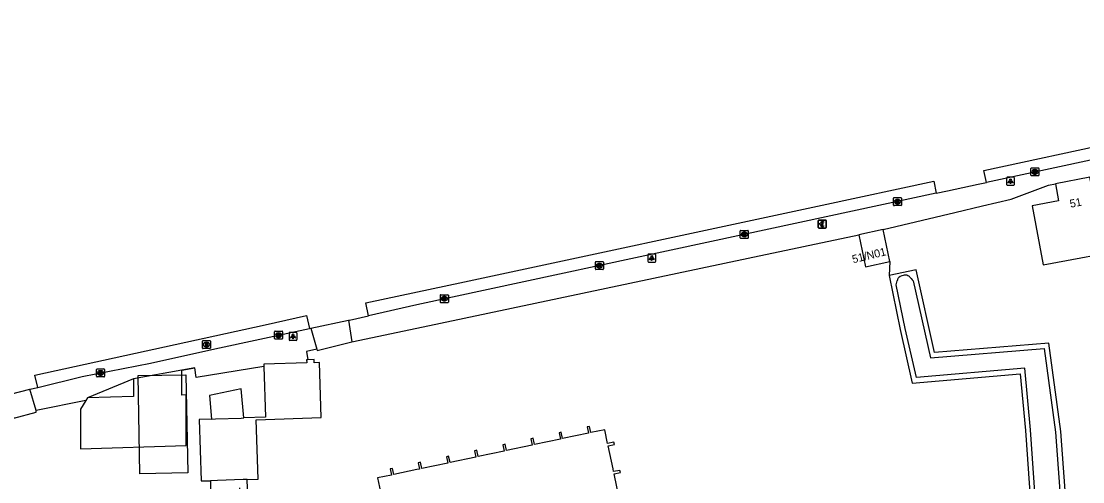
# Model space of a CAD drawing. Extents: x 161772 to 163123, y 383092 to 383917.
# Drawn here: x 161950.6 to 162083.2, y 383706.8 to 383764.3 of the extents above; entities that cross this region are included whole.
import ezdxf

# ---------------------------------------------------------------- set-up
doc = ezdxf.new("R2010")
doc.units = 0
for name, color, linetype in [('IMGEO_Betaalautomaat', 7, 'Continuous'), ('IMGEO_Erf', 7, 'Continuous'), ('IMGEO_Hek', 7, 'Continuous'), ('IMGEO_Kolk', 7, 'Continuous'), ('IMGEO_Lichtpunt', 7, 'Continuous'), ('IMGEO_Meer_plas_ven_vijver', 7, 'Continuous'), ('IMGEO_Muur', 7, 'Continuous'), ('IMGEO_Pand', 7, 'Continuous'), ('IMGEO_Pand_nummerreeks', 7, 'Continuous'), ('IMGEO_Pand_vergunning_verleend', 7, 'Continuous'), ('IMGEO_Rijbaan_lokaal_open', 7, 'Continuous'), ('IMGEO_Rioolput', 7, 'Continuous'), ('IMGEO_Voetpad_open', 7, 'Continuous'), ('IMGEO_Waterloop', 7, 'Continuous')]:
    doc.layers.add(name, color=color, linetype=linetype)

msp = doc.modelspace()

# ---------------------------------------------------------------- linework, layer by layer
at = {"layer": 'IMGEO_Betaalautomaat'}
for p, q in [((162050.16, 383738.51), (162050.16, 383739.36)), ((162050.16, 383739.36), (162050.16, 383738.51)), ((162050.23, 383739.44), (162051.07, 383739.44)), ((162051.07, 383739.44), (162050.23, 383739.44)), ((162051.08, 383738.44), (162050.24, 383738.44)), ((162050.24, 383738.44), (162051.08, 383738.44)), ((162050.44, 383738.9), (162050.44, 383738.97)), ((162050.56, 383738.97), (162050.56, 383738.9)), ((162050.82, 383739.24), (162050.8, 383739.14)), ((162050.81, 383738.74), (162050.83, 383738.65)), ((162051.16, 383739.37), (162051.16, 383738.52)), ((162051.16, 383738.52), (162051.16, 383739.37))]:
    msp.add_line(p, q, dxfattribs=at)
for points in [[(162050.44, 383738.97), (162050.37, 383738.97), (162050.37, 383739.04), (162050.45, 383739.04)], [(162050.45, 383738.83), (162050.37, 383738.83), (162050.37, 383738.9), (162050.44, 383738.9)], [(162050.57, 383739.04), (162050.72, 383739.04), (162050.72, 383738.97), (162050.56, 383738.97)], [(162050.56, 383738.9), (162050.72, 383738.9), (162050.72, 383738.83), (162050.57, 383738.83)]]:
    msp.add_lwpolyline(points, dxfattribs=at)
for centre, radius, start, end in [((162050.24, 383739.36), 0.0779, 92.4484, 184.2845), ((162050.24, 383739.36), 0.0779, 92.4484, 184.2845), ((162050.24, 383738.52), 0.0779, 182.4484, 274.2845), ((162050.24, 383738.52), 0.0779, 182.4484, 274.2845), ((162050.73, 383738.96), 0.293, 73.014, 165.0139), ((162050.71, 383738.89), 0.267, 191.8096, 297.0389), ((162050.74, 383738.98), 0.179, 69.3236, 159.5683), ((162050.74, 383738.9), 0.179, 202.7625, 291.8693), ((162051.08, 383739.36), 0.0779, 2.4484, 94.2845), ((162051.08, 383739.36), 0.0779, 2.4484, 94.2845), ((162051.08, 383738.52), 0.0779, 272.4484, 4.2845), ((162051.08, 383738.52), 0.0779, 272.4484, 4.2845)]:
    msp.add_arc(centre, radius, start, end, dxfattribs=at)
at = {"layer": 'IMGEO_Erf'}
for points in [[(162085.98, 383637.64), (162080.45, 383713.03), (162078.95, 383724.08), (162064.69, 383722.91), (162062.37, 383733.24), (162059, 383732.53), (162060.37, 383725.77), (162061.9, 383719.08), (162075.38, 383720.25), (162076.03, 383713.17), (162081.29, 383637.92)], [(161974.24, 383706.88), (161975.57, 383631.41)], [(161979.13, 383699.38), (161978.84, 383707.03)]]:
    msp.add_lwpolyline(points, dxfattribs=at)
at = {"layer": 'IMGEO_Hek'}
msp.add_lwpolyline([(162059.12, 383734.27), (162059, 383732.53)], dxfattribs=at)
at = {"layer": 'IMGEO_Kolk'}
for p, q in [((162076.73, 383745.03), (162076.73, 383745.89)), ((162076.8, 383745.96), (162077.65, 383745.96)), ((162077.21, 383745.74), (162077.24, 383745.74)), ((162077.24, 383745.18), (162077.21, 383745.18)), ((162077.73, 383745.89), (162077.73, 383745.03)), ((162077.65, 383744.96), (162076.8, 383744.96)), ((162059.56, 383741.31), (162059.56, 383742.16)), ((162059.63, 383742.24), (162060.48, 383742.24)), ((162060.48, 383741.24), (162059.63, 383741.24)), ((162060.04, 383742.02), (162060.07, 383742.02)), ((162060.07, 383741.46), (162060.04, 383741.46)), ((162060.56, 383742.16), (162060.56, 383741.31)), ((162040.42, 383737.22), (162040.42, 383738.08)), ((162040.49, 383738.15), (162041.35, 383738.15)), ((162041.35, 383737.15), (162040.49, 383737.15)), ((162040.91, 383737.93), (162040.93, 383737.93)), ((162040.93, 383737.37), (162040.91, 383737.37)), ((162041.42, 383738.08), (162041.42, 383737.22)), ((162022.32, 383733.33), (162022.32, 383734.18)), ((162022.39, 383734.26), (162023.25, 383734.26)), ((162023.25, 383733.25), (162022.39, 383733.25)), ((162022.83, 383733.48), (162022.8, 383733.48)), ((162022.81, 383734.03), (162022.83, 383734.03)), ((162023.32, 383734.18), (162023.32, 383733.33)), ((162002.95, 383729.19), (162002.95, 383730.04)), ((162003.02, 383730.12), (162003.88, 383730.12)), ((162003.88, 383729.12), (162003.02, 383729.12)), ((162003.46, 383729.34), (162003.43, 383729.34)), ((162003.44, 383729.9), (162003.46, 383729.9)), ((162003.95, 383730.04), (162003.95, 383729.19)), ((161982.24, 383724.64), (161982.24, 383725.49)), ((161982.32, 383725.56), (161983.17, 383725.56)), ((161982.73, 383725.34), (161982.75, 383725.34)), ((161983.24, 383725.49), (161983.24, 383724.64)), ((161983.17, 383724.56), (161982.32, 383724.56)), ((161982.75, 383724.78), (161982.73, 383724.78)), ((161960, 383719.93), (161960, 383720.78)), ((161960.08, 383720.85), (161960.93, 383720.85)), ((161960.93, 383719.85), (161960.08, 383719.85)), ((161960.49, 383720.63), (161960.52, 383720.63)), ((161960.51, 383720.07), (161960.49, 383720.07)), ((161961, 383720.78), (161961, 383719.93))]:
    msp.add_line(p, q, dxfattribs=at)
for points in [[(162076.73, 383745.03), (162076.73, 383745.89)], [(162076.8, 383745.96), (162077.65, 383745.96)], [(162077.05, 383745.66), (162077.17, 383745.66), (162077.17, 383745.51), (162077.3, 383745.66), (162077.46, 383745.66), (162077.32, 383745.51), (162077.47, 383745.26), (162077.32, 383745.26), (162077.23, 383745.42), (162077.17, 383745.36), (162077.17, 383745.26), (162077.05, 383745.26), (162077.05, 383745.66)], [(162077.73, 383745.89), (162077.73, 383745.03)], [(162077.65, 383744.96), (162076.8, 383744.96)], [(162059.56, 383741.31), (162059.56, 383742.16)], [(162059.63, 383742.24), (162060.48, 383742.24)], [(162060.48, 383741.24), (162059.63, 383741.24)], [(162059.88, 383741.94), (162060, 383741.94), (162060, 383741.79), (162060.13, 383741.94), (162060.29, 383741.94), (162060.15, 383741.79), (162060.3, 383741.54), (162060.15, 383741.54), (162060.06, 383741.7), (162060, 383741.63), (162060, 383741.54), (162059.88, 383741.54), (162059.88, 383741.94)], [(162060.56, 383742.16), (162060.56, 383741.31)], [(162040.42, 383737.22), (162040.42, 383738.08)], [(162040.49, 383738.15), (162041.35, 383738.15)], [(162041.35, 383737.15), (162040.49, 383737.15)], [(162040.74, 383737.85), (162040.86, 383737.85), (162040.86, 383737.7), (162040.99, 383737.85), (162041.16, 383737.85), (162041.01, 383737.7), (162041.16, 383737.45), (162041.01, 383737.45), (162040.93, 383737.61), (162040.86, 383737.55), (162040.86, 383737.45), (162040.74, 383737.45), (162040.74, 383737.85)], [(162041.42, 383738.08), (162041.42, 383737.22)], [(162022.32, 383733.33), (162022.32, 383734.18)], [(162022.39, 383734.26), (162023.25, 383734.26)], [(162023.25, 383733.25), (162022.39, 383733.25)], [(162022.64, 383733.95), (162022.76, 383733.95), (162022.76, 383733.8), (162022.89, 383733.95), (162023.06, 383733.95), (162022.91, 383733.8), (162023.06, 383733.55), (162022.91, 383733.55), (162022.83, 383733.72), (162022.76, 383733.65), (162022.76, 383733.55), (162022.64, 383733.55), (162022.64, 383733.95)], [(162023.32, 383734.18), (162023.32, 383733.33)], [(162002.95, 383729.19), (162002.95, 383730.04)], [(162003.02, 383730.12), (162003.88, 383730.12)], [(162003.88, 383729.12), (162003.02, 383729.12)], [(162003.27, 383729.82), (162003.39, 383729.82), (162003.39, 383729.66), (162003.52, 383729.82), (162003.69, 383729.82), (162003.54, 383729.67), (162003.69, 383729.42), (162003.54, 383729.42), (162003.46, 383729.58), (162003.39, 383729.51), (162003.39, 383729.42), (162003.27, 383729.42), (162003.27, 383729.82)], [(162003.95, 383730.04), (162003.95, 383729.19)], [(161982.24, 383724.64), (161982.24, 383725.49)], [(161982.32, 383725.56), (161983.17, 383725.56)], [(161982.56, 383725.26), (161982.69, 383725.26), (161982.69, 383725.11), (161982.81, 383725.26), (161982.98, 383725.26), (161982.83, 383725.11), (161982.99, 383724.86), (161982.83, 383724.86), (161982.75, 383725.03), (161982.69, 383724.96), (161982.69, 383724.86), (161982.56, 383724.86), (161982.56, 383725.26)], [(161983.24, 383725.49), (161983.24, 383724.64)], [(161983.17, 383724.56), (161982.32, 383724.56)], [(161960, 383719.93), (161960, 383720.78)], [(161960.08, 383720.85), (161960.93, 383720.85)], [(161960.93, 383719.85), (161960.08, 383719.85)], [(161960.32, 383720.55), (161960.45, 383720.55), (161960.45, 383720.4), (161960.58, 383720.55), (161960.74, 383720.55), (161960.6, 383720.4), (161960.75, 383720.15), (161960.6, 383720.15), (161960.51, 383720.32), (161960.45, 383720.25), (161960.45, 383720.15), (161960.32, 383720.15), (161960.32, 383720.55)], [(161961, 383720.78), (161961, 383719.93)]]:
    msp.add_lwpolyline(points, dxfattribs=at)
for centre, start, end in [((162076.8, 383745.88), 91.552, 178.448), ((162076.8, 383745.88), 91.552, 178.448), ((162076.8, 383745.04), 181.552, 268.448), ((162076.8, 383745.04), 181.552, 268.448), ((162077.65, 383745.88), 1.552, 88.448), ((162077.65, 383745.88), 1.552, 88.448), ((162077.65, 383745.04), 271.552, 358.448), ((162077.65, 383745.04), 271.552, 358.448), ((162059.63, 383742.16), 91.552, 178.448), ((162059.63, 383742.16), 91.552, 178.448), ((162059.63, 383741.31), 181.552, 268.448), ((162059.63, 383741.31), 181.552, 268.448), ((162060.48, 383742.16), 1.552, 88.448), ((162060.48, 383742.16), 1.552, 88.448), ((162060.48, 383741.31), 271.552, 358.448), ((162060.48, 383741.31), 271.552, 358.448), ((162040.5, 383738.07), 91.552, 178.448), ((162040.5, 383738.07), 91.552, 178.448), ((162040.5, 383737.22), 181.552, 268.448), ((162040.5, 383737.22), 181.552, 268.448), ((162041.34, 383738.07), 1.552, 88.448), ((162041.34, 383738.07), 1.552, 88.448), ((162041.34, 383737.22), 271.552, 358.448), ((162041.34, 383737.22), 271.552, 358.448), ((162022.39, 383734.18), 91.552, 178.448), ((162022.39, 383734.18), 91.552, 178.448), ((162022.39, 383733.33), 181.552, 268.448), ((162022.39, 383733.33), 181.552, 268.448), ((162023.24, 383734.18), 1.552, 88.448), ((162023.24, 383734.18), 1.552, 88.448), ((162023.24, 383733.33), 271.552, 358.448), ((162023.24, 383733.33), 271.552, 358.448), ((162003.02, 383730.04), 91.552, 178.448), ((162003.02, 383730.04), 91.552, 178.448), ((162003.02, 383729.19), 181.552, 268.448), ((162003.02, 383729.19), 181.552, 268.448), ((162003.87, 383730.04), 1.552, 88.448), ((162003.87, 383730.04), 1.552, 88.448), ((162003.87, 383729.19), 271.552, 358.448), ((162003.87, 383729.19), 271.552, 358.448), ((161982.32, 383725.49), 91.552, 178.448), ((161982.32, 383725.49), 91.552, 178.448), ((161983.17, 383725.49), 1.552, 88.448), ((161983.17, 383725.49), 1.552, 88.448), ((161982.32, 383724.64), 181.552, 268.448), ((161982.32, 383724.64), 181.552, 268.448), ((161983.17, 383724.64), 271.552, 358.448), ((161983.17, 383724.64), 271.552, 358.448), ((161960.08, 383720.78), 91.552, 178.448), ((161960.08, 383720.78), 91.552, 178.448), ((161960.08, 383719.93), 181.552, 268.448), ((161960.08, 383719.93), 181.552, 268.448), ((161960.93, 383720.78), 1.552, 88.448), ((161960.93, 383720.78), 1.552, 88.448), ((161960.93, 383719.93), 271.552, 358.448), ((161960.93, 383719.93), 271.552, 358.448)]:
    msp.add_arc(centre, 0.0765, start, end, dxfattribs=at)
for centre, major_axis, ratio, start_param, end_param in [((162077.21, 383745.46), (-0.387, 0.002), 0.722429, 4.712389, 7.853982), ((162077.24, 383745.46), (-0.39, 0.002), 0.717154, 1.570796, 4.712389), ((162060.04, 383741.74), (-0.387, 0.002), 0.722429, 4.712389, 7.853982), ((162060.07, 383741.74), (-0.39, 0.002), 0.717154, 1.570796, 4.712389), ((162040.91, 383737.65), (-0.387, 0.002), 0.722429, 4.712389, 7.853982), ((162040.93, 383737.65), (-0.39, 0.002), 0.717154, 1.570796, 4.712389), ((162022.81, 383733.75), (-0.387, 0.002), 0.722429, 4.712389, 7.853982), ((162022.83, 383733.75), (-0.39, 0.002), 0.717154, 1.570796, 4.712389), ((162003.44, 383729.62), (-0.387, 0.002), 0.722429, 4.712389, 7.853982), ((162003.46, 383729.62), (-0.39, 0.002), 0.717154, 1.570796, 4.712389), ((161982.73, 383725.06), (-0.387, 0.002), 0.722429, 4.712389, 7.853982), ((161982.75, 383725.06), (-0.39, 0.002), 0.717154, 1.570796, 4.712389), ((161960.49, 383720.35), (-0.387, 0.002), 0.722429, 4.712389, 7.853982), ((161960.51, 383720.35), (-0.39, 0.002), 0.717154, 1.570796, 4.712389)]:
    msp.add_ellipse(centre, major_axis=major_axis, ratio=ratio, start_param=start_param, end_param=end_param, dxfattribs=at)
at = {"layer": 'IMGEO_Lichtpunt'}
for p, q in [((162073.67, 383744.69), (162073.67, 383743.89)), ((162073.67, 383744.69), (162073.67, 383743.89)), ((162074.58, 383744.79), (162073.77, 383744.79)), ((162074.58, 383744.79), (162073.77, 383744.79)), ((162073.77, 383743.79), (162074.58, 383743.79)), ((162073.77, 383743.79), (162074.58, 383743.79)), ((162074.67, 383743.89), (162074.67, 383744.69)), ((162074.67, 383743.89), (162074.67, 383744.69)), ((162028.87, 383735.1), (162028.87, 383734.29)), ((162028.87, 383735.1), (162028.87, 383734.29)), ((162029.77, 383735.19), (162028.96, 383735.19)), ((162029.77, 383735.19), (162028.96, 383735.19)), ((162029.86, 383734.29), (162029.86, 383735.1)), ((162029.86, 383734.29), (162029.86, 383735.1)), ((162028.96, 383734.2), (162029.77, 383734.2)), ((162028.96, 383734.2), (162029.77, 383734.2)), ((161984.05, 383725.32), (161984.05, 383724.51)), ((161984.05, 383725.32), (161984.05, 383724.51)), ((161984.95, 383725.41), (161984.15, 383725.41)), ((161984.95, 383725.41), (161984.15, 383725.41)), ((161985.05, 383724.51), (161985.05, 383725.32)), ((161985.05, 383724.51), (161985.05, 383725.32)), ((161984.15, 383724.42), (161984.95, 383724.42)), ((161984.15, 383724.42), (161984.95, 383724.42))]:
    msp.add_line(p, q, dxfattribs=at)
for points in [[(162074.05, 383744.36), (162074.09, 383744.33), (162073.9, 383744.07), (162073.86, 383744.1), (162074.05, 383744.36)], [(162074.15, 383744.31), (162074.2, 383744.31), (162074.2, 383743.99), (162074.15, 383743.99), (162074.15, 383744.31)], [(162074.26, 383744.33), (162074.3, 383744.36), (162074.49, 383744.09), (162074.45, 383744.07), (162074.26, 383744.33)], [(162029.24, 383734.76), (162029.28, 383734.74), (162029.09, 383734.47), (162029.05, 383734.5), (162029.24, 383734.76)], [(162029.34, 383734.72), (162029.39, 383734.72), (162029.39, 383734.39), (162029.34, 383734.39), (162029.34, 383734.72)], [(162029.45, 383734.74), (162029.49, 383734.76), (162029.68, 383734.5), (162029.64, 383734.47), (162029.45, 383734.74)], [(161984.43, 383724.98), (161984.46, 383724.96), (161984.28, 383724.69), (161984.24, 383724.72), (161984.43, 383724.98)], [(161984.53, 383724.94), (161984.58, 383724.94), (161984.58, 383724.61), (161984.53, 383724.61), (161984.53, 383724.94)], [(161984.64, 383724.96), (161984.68, 383724.98), (161984.86, 383724.72), (161984.82, 383724.69), (161984.64, 383724.96)]]:
    msp.add_lwpolyline(points, dxfattribs=at)
for centre in [(162074.17, 383744.49), (162029.37, 383734.9), (161984.55, 383725.12)]:
    msp.add_circle(centre, 0.0994, dxfattribs=at)
for centre, start, end in [((162073.77, 383744.69), 90, 180), ((162073.77, 383744.69), 90, 180), ((162073.77, 383743.89), 180, 270), ((162073.77, 383743.89), 180, 270), ((162074.58, 383744.69), 0, 90), ((162074.58, 383744.69), 0, 90), ((162074.58, 383743.89), 270, 0), ((162074.58, 383743.89), 270, 360), ((162028.96, 383735.1), 90, 180), ((162028.96, 383735.1), 90, 180), ((162029.77, 383735.1), 0, 90), ((162029.77, 383735.1), 0, 90), ((162028.96, 383734.29), 180, 270), ((162028.96, 383734.29), 180, 270), ((162029.77, 383734.29), 270, 0), ((162029.77, 383734.29), 270, 360), ((161984.15, 383725.32), 90, 180), ((161984.15, 383725.32), 90, 180), ((161984.95, 383725.32), 0, 90), ((161984.95, 383725.32), 0, 90), ((161984.15, 383724.51), 180, 270), ((161984.15, 383724.51), 180, 270), ((161984.95, 383724.51), 270, 0), ((161984.95, 383724.51), 270, 360)]:
    msp.add_arc(centre, 0.0946, start, end, dxfattribs=at)
at = {"layer": 'IMGEO_Meer_plas_ven_vijver'}
msp.add_lwpolyline([(161978.4, 383714.72), (161978.07, 383718.37), (161974.11, 383717.54), (161974.35, 383714.59)], dxfattribs=at)
at = {"layer": 'IMGEO_Muur'}
for points in [[(161970.65, 383720.71), (161972.28, 383721)], [(161958.68, 383716.9), (161952.45, 383715.66)]]:
    msp.add_lwpolyline(points, dxfattribs=at)
at = {"layer": 'IMGEO_Pand'}
for points in [[(162079.78, 383743.97), (162080.18, 383741.83), (162076.86, 383741.21), (162078.24, 383733.84), (162089.44, 383735.94), (162088.06, 383743.31), (162084.49, 383742.64), (162084.08, 383744.78)], [(162084.08, 383744.78), (162079.78, 383743.97)], [(162058.26, 383738.28), (162055.21, 383737.6)], [(162055.21, 383737.6), (162056.08, 383733.59), (162059.12, 383734.27), (162058.26, 383738.28)], [(161980.92, 383721.17), (161981.13, 383714.81), (161978.4, 383714.72)], [(161978.84, 383707.03), (161980.18, 383707.08), (161979.94, 383714.49), (161988.08, 383714.76), (161987.86, 383721.65), (161987.2, 383721.62), (161987.19, 383722.03), (161986.38, 383722)], [(161986.38, 383722), (161986.25, 383721.99), (161986.27, 383721.61), (161980.91, 383721.44), (161980.92, 383721.17)], [(161958.68, 383716.9), (161958.02, 383715.83), (161958.02, 383710.88), (161971.22, 383711.27), (161971.22, 383717.6), (161970.64, 383717.58), (161970.65, 383720.71)], [(161970.65, 383720.71), (161964.64, 383719.62)], [(161964.64, 383719.62), (161964.64, 383717.4), (161958.89, 383717.23)], [(161958.89, 383717.23), (161958.68, 383716.9)], [(161974.35, 383714.59), (161972.84, 383714.54), (161973.09, 383706.85), (161974.24, 383706.88)], [(161974.35, 383714.59), (161974.85, 383714.6), (161978.09, 383714.71), (161978.4, 383714.72)], [(162025.35, 383704.49), (162024.66, 383707.74), (162025.45, 383707.91), (162025.39, 383708.18), (162024.6, 383708.02), (162024.52, 383708.37), (162023.91, 383711.25), (162024.69, 383711.42), (162024.63, 383711.7), (162023.85, 383711.53), (162023.48, 383713.26), (162021.74, 383712.89), (162021.58, 383713.67), (162021.3, 383713.61), (162021.47, 383712.83), (162018.23, 383712.14), (162018.06, 383712.93), (162017.78, 383712.87), (162017.95, 383712.08), (162014.72, 383711.4), (162014.55, 383712.19), (162014.26, 383712.12), (162014.43, 383711.33), (162011.21, 383710.65), (162011.04, 383711.44), (162010.75, 383711.38), (162010.92, 383710.59), (162007.69, 383709.9), (162007.52, 383710.68), (162007.23, 383710.62), (162007.4, 383709.84), (162004.16, 383709.15), (162003.99, 383709.94), (162003.72, 383709.88), (162003.88, 383709.09), (162000.64, 383708.4), (162000.48, 383709.19), (162000.19, 383709.13), (162000.36, 383708.34), (162000, 383708.27), (161997.14, 383707.66), (161996.97, 383708.43), (161996.68, 383708.38), (161996.84, 383707.59), (161995.12, 383707.23), (161995.48, 383705.51)], [(161978.84, 383707.03), (161978.32, 383707.02), (161975.12, 383706.91), (161974.24, 383706.88)]]:
    msp.add_lwpolyline(points, dxfattribs=at)
at = {"layer": 'IMGEO_Pand_vergunning_verleend'}
msp.add_lwpolyline([(161965.2, 383720.02), (161971.16, 383720.13), (161971.39, 383707.87), (161965.43, 383707.75), (161965.2, 383720.02)], dxfattribs=at)
at = {"layer": 'IMGEO_Rijbaan_lokaal_open'}
for points in [[(162071.16, 383744.13), (162070.83, 383745.65), (162087.46, 383749.22), (162116.59, 383755.47), (162143.1, 383761.16), (162157.04, 383764.27), (162157.36, 383762.66)], [(161993.98, 383727.48), (161993.66, 383729.1), (162005.96, 383731.73), (162050.66, 383741.32), (162064.6, 383744.31), (162064.89, 383742.78)], [(162064.89, 383742.78), (162066.3, 383743.09), (162070.13, 383743.91), (162071.16, 383744.13)], [(161952.65, 383718.54), (161952.31, 383720.05), (161981.08, 383726.37), (161986.25, 383727.5), (161986.59, 383725.88)], [(161986.77, 383725.92), (161991.47, 383726.92)], [(161991.47, 383726.92), (161991.61, 383726.95), (161993.98, 383727.48)], [(161986.59, 383725.88), (161986.77, 383725.92)], [(161951.69, 383718.3), (161952.65, 383718.54)], [(161947.93, 383717.38), (161951.69, 383718.3)]]:
    msp.add_lwpolyline(points, dxfattribs=at)
at = {"layer": 'IMGEO_Rioolput'}
for p, q in [((161973.24, 383723.46), (161973.24, 383724.32)), ((161973.31, 383724.39), (161974.16, 383724.39)), ((161973.72, 383724.17), (161973.75, 383724.17)), ((161974.24, 383724.32), (161974.24, 383723.46)), ((161974.16, 383723.39), (161973.31, 383723.39)), ((161973.75, 383723.61), (161973.72, 383723.61))]:
    msp.add_line(p, q, dxfattribs=at)
for points in [[(161973.24, 383723.46), (161973.24, 383724.32)], [(161973.31, 383724.39), (161974.16, 383724.39)], [(161973.82, 383724.09), (161973.57, 383724.09), (161973.57, 383723.69)], [(161973.57, 383723.69), (161973.7, 383723.69), (161973.7, 383723.85), (161973.71, 383723.85)], [(161973.75, 383724.01), (161973.7, 383724.01), (161973.7, 383723.93)], [(161973.7, 383723.93), (161973.75, 383723.93)], [(161973.75, 383723.82), (161973.83, 383723.69), (161973.96, 383723.69), (161973.9, 383723.82)], [(161974.24, 383724.32), (161974.24, 383723.46)], [(161974.16, 383723.39), (161973.31, 383723.39)]]:
    msp.add_lwpolyline(points, dxfattribs=at)
for centre, radius, start, end in [((161973.31, 383724.32), 0.0765, 91.552, 178.448), ((161973.31, 383724.32), 0.0765, 91.552, 178.448), ((161973.71, 383723.8), 0.0533, 26.0293, 88.6989), ((161973.76, 383723.91), 0.0964, 77.0061, 93.1865), ((161973.73, 383724.12), 0.19, 274.7715, 282.9687), ((161973.77, 383723.97), 0.0378, 276.6634, 79.6772), ((161973.82, 383723.98), 0.109, 350.3612, 89.416), ((161973.82, 383723.98), 0.112, 277.5842, 350.9817), ((161973.81, 383723.76), 0.108, 29.5134, 73.7905), ((161974.16, 383724.32), 0.0765, 1.552, 88.448), ((161974.16, 383724.32), 0.0765, 1.552, 88.448), ((161973.31, 383723.47), 0.0765, 181.552, 268.448), ((161973.31, 383723.47), 0.0765, 181.552, 268.448), ((161974.16, 383723.47), 0.0765, 271.552, 358.448), ((161974.16, 383723.47), 0.0765, 271.552, 358.448)]:
    msp.add_arc(centre, radius, start, end, dxfattribs=at)
for centre, major_axis, ratio, start_param, end_param in [((161973.72, 383723.89), (-0.387, 0.002), 0.722429, 4.712389, 7.853982), ((161973.75, 383723.89), (-0.39, 0.002), 0.717154, 1.570796, 4.712389)]:
    msp.add_ellipse(centre, major_axis=major_axis, ratio=ratio, start_param=start_param, end_param=end_param, dxfattribs=at)
at = {"layer": 'IMGEO_Voetpad_open'}
for points in [[(162157.36, 383762.66), (162098.5, 383750), (162096.36, 383749.54), (162092.7, 383748.76), (162071.16, 383744.13)], [(162058.26, 383738.28), (162067.24, 383740.4), (162070.69, 383741.22), (162074.26, 383742.06), (162078.9, 383743.79), (162079.78, 383743.97)], [(162064.89, 383742.78), (162040.71, 383737.59), (162000, 383728.84), (161993.98, 383727.48)], [(161991.9, 383724.24), (162000, 383725.95), (162041.4, 383734.68), (162055.21, 383737.6)], [(161991.47, 383726.92), (161991.9, 383724.24)], [(161952.65, 383718.54), (161958.19, 383719.9), (161966.74, 383721.58), (161974.77, 383723.37), (161986.59, 383725.88)], [(161986.77, 383725.92), (161987.51, 383723.3)], [(161987.51, 383723.3), (161987.58, 383723.13), (161991.9, 383724.24)], [(161987.51, 383723.3), (161986.23, 383723.03), (161986.38, 383722)], [(161980.92, 383721.17), (161972.46, 383719.78), (161972.28, 383721), (161970.65, 383720.71)], [(161964.64, 383719.62), (161958.89, 383717.23)], [(161952.45, 383715.66), (161951.69, 383718.3)], [(161958.68, 383716.9), (161952.45, 383715.66)], [(161949.49, 383714.87), (161949.61, 383714.91), (161949.68, 383714.69), (161952.45, 383715.46), (161952.45, 383715.66)]]:
    msp.add_lwpolyline(points, dxfattribs=at)
at = {"layer": 'IMGEO_Waterloop'}
for points in [[(161977.88, 383705.99), (161978.12, 383699.35), (161978.65, 383673.1), (161978.78, 383633.22), (161982.69, 383633.02), (161989.58, 383633.34), (161990.03, 383633.36), (161995.22, 383634.32), (161995.7, 383634.33), (162000.02, 383634.53), (162032.41, 383636.08), (162033.02, 383636.03), (162037.66, 383634.76), (162037.85, 383634.7), (162037.96, 383634.71), (162050.99, 383635.62), (162081.98, 383637.31), (162076.67, 383713.22), (162075.97, 383720.95), (162062.41, 383719.77), (162061, 383725.91), (162059.9, 383731.35), (162059.98, 383731.7), (162060.02, 383731.87)], [(162060.39, 383732.4), (162060.47, 383732.44)], [(162061.68, 383732.23), (162061.77, 383732.13), (162061.89, 383731.99), (162062.03, 383731.83), (162064.18, 383722.22), (162078.39, 383723.39), (162079.81, 383712.96), (162085.37, 383637.05), (162098.23, 383635.79), (162098.48, 383635.77), (162103.08, 383634.74), (162103.53, 383634.7), (162130.28, 383634.64), (162185.82, 383629.99), (162186.26, 383666.03)]]:
    msp.add_lwpolyline(points, dxfattribs=at)
for centre, radius, start, end in [((162061.22, 383731.55), 1.25, 148.7705, 165.1711), ((162060.66, 383731.85), 0.612, 116.3396, 145.5078), ((162061.05, 383731.17), 1.39, 102.0286, 114.604), ((162061.14, 383731.02), 1.56, 94.1238, 103.9552), ((162061.06, 383732.01), 0.568, 57.5156, 93.215), ((162060.51, 383731.13), 1.61, 43.0304, 57.7851)]:
    msp.add_arc(centre, radius, start, end, dxfattribs=at)

# ---------------------------------------------------------------- texts
at = {"layer": 'IMGEO_Pand_nummerreeks'}
for s, rotation, p in [('51', 11.0515, (162081.68, 383740.97)), ('51/N01', 13.5909, (162054.52, 383734.04))]:
    msp.add_text(s, height=1, rotation=rotation, dxfattribs=at).set_placement(p)

doc.saveas('drawing.dxf')
